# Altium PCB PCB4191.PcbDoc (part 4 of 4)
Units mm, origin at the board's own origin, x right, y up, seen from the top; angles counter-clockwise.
Board outline 160 x 160 mm, 6 copper layers (Top Layer, IM1 RIS, IM2 Signal, IM3 Signal, IM4 GND, Bottom Layer), stack 1.582 mm thick; 143 components, 121 nets, 430 pads, 4983 vias.
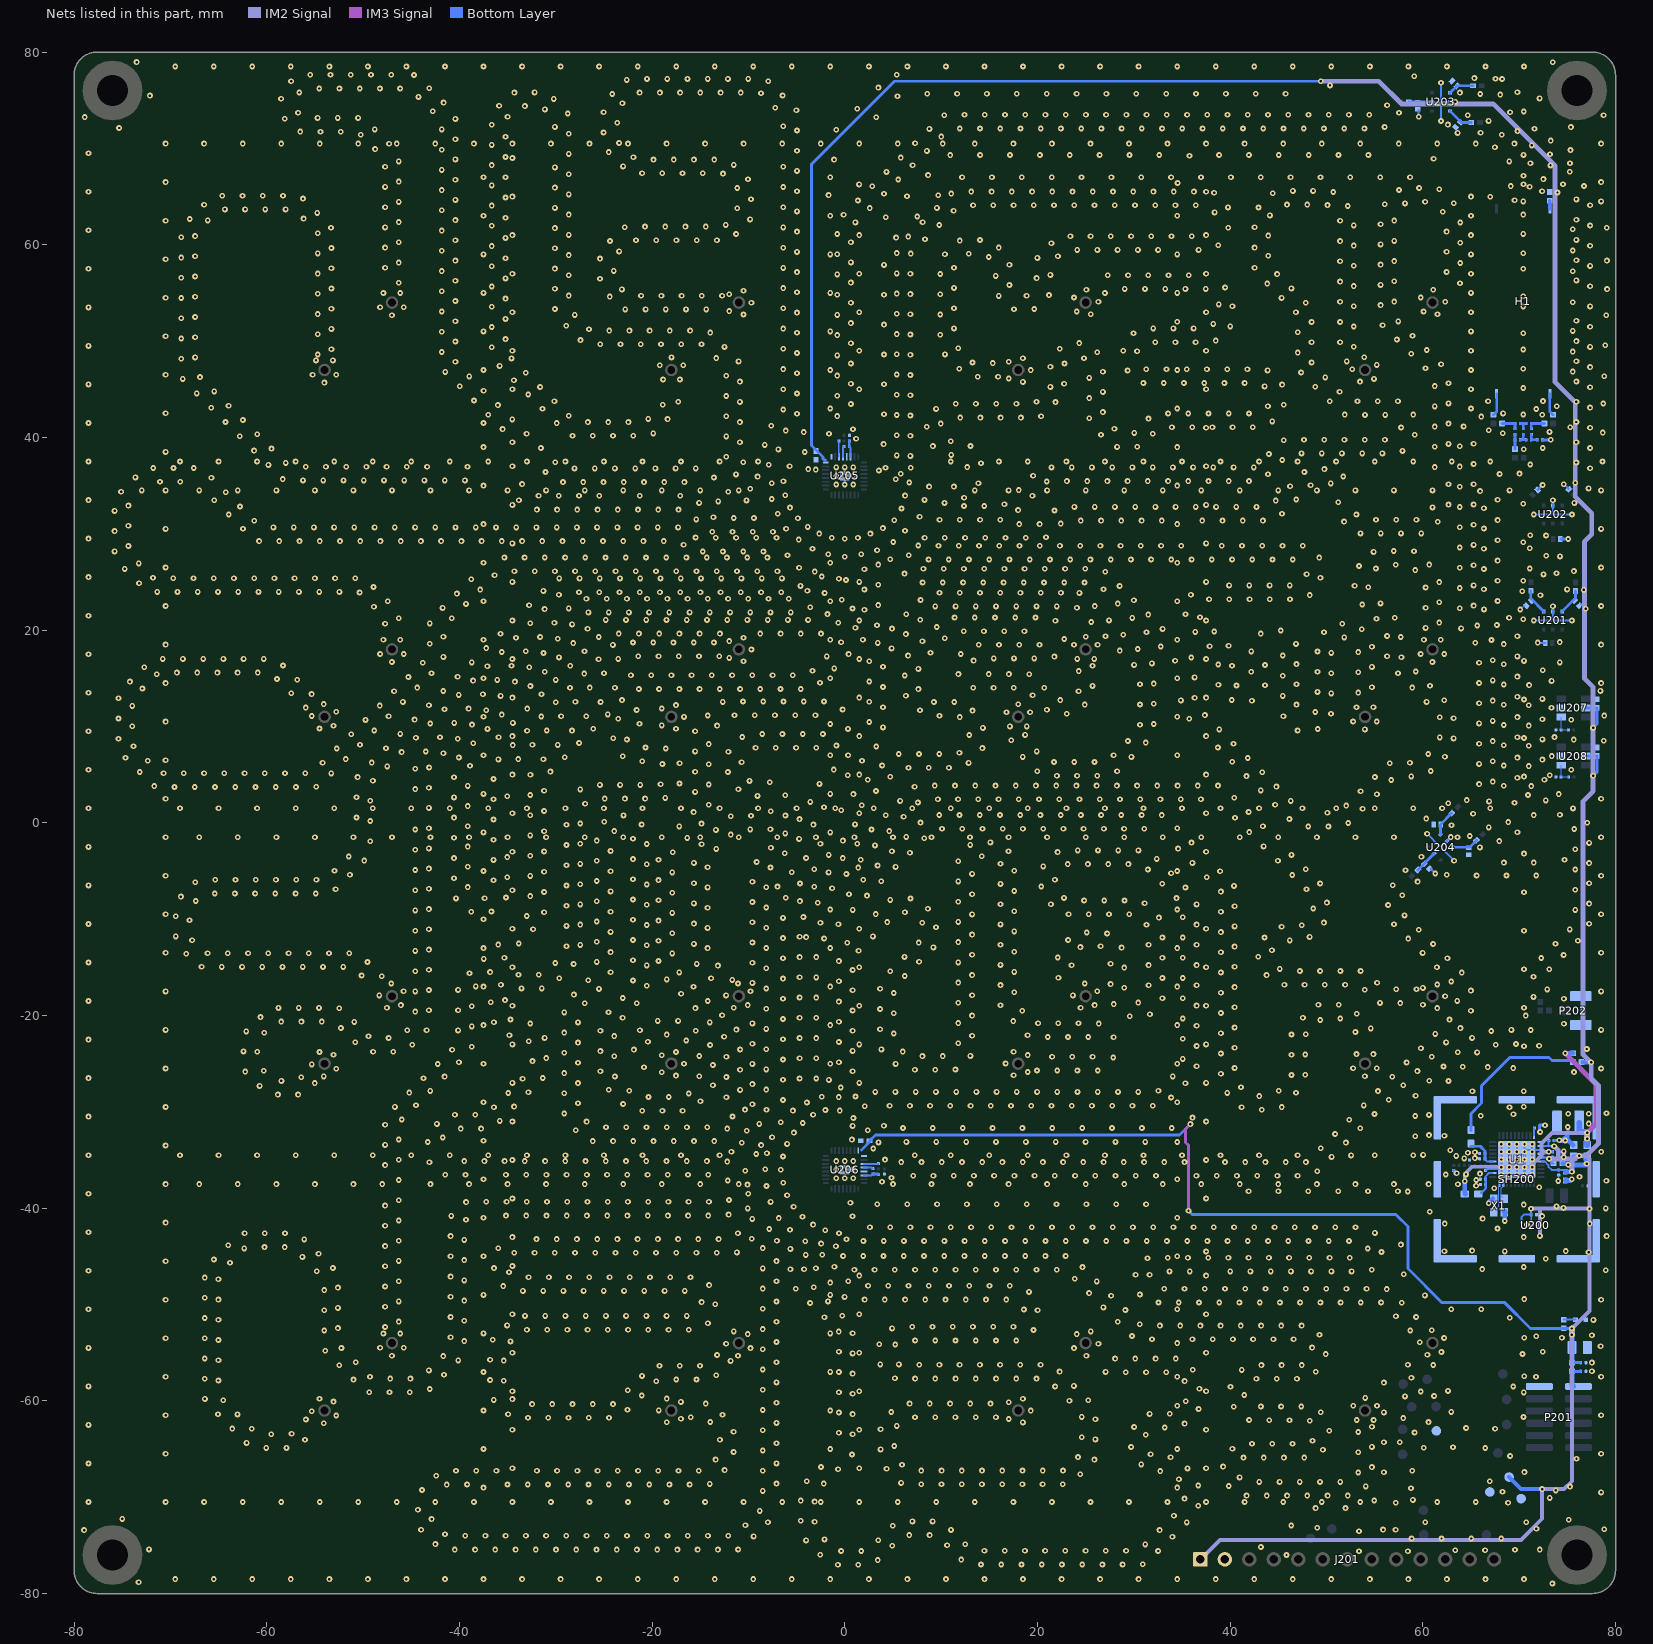
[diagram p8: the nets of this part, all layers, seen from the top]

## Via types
v1: diameter 0.6, hole 0.25, IM4 GND to Bottom Layer, tented bottom, 3953 vias
v2: diameter 0.6, hole 0.25, Top Layer to Bottom Layer, tented both sides, 851 vias
v3: diameter 0.6, hole 0.25, IM4 GND to Bottom Layer, tented both sides, 179 vias

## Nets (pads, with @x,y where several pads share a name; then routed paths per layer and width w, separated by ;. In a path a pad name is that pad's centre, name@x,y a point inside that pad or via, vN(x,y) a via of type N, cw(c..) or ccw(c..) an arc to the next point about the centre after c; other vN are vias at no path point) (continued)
GND: (continued)
  other v1: -14.877,49.663 0.637,49.77 24.333,49.787 32.213,49.888 34.313,49.888 36.413,49.888 48.45,49.876 51.413,49.879 -40.413,49.956 75.938,50.001 38.507,50.048 -27.432,50.099 57.307,50.161 -35.213,50.206 -68.862,50.268 -67.438,50.401 58.926,50.556 -0.787,50.617 9.913,50.658 6.812,50.68 -54.712,50.703 5.388,50.729 29.964,50.821 -13.969,50.876 -4.963,50.86 47.025,50.908 -41.837,50.969 65,51 -24.458,51.087 -22.358,51.087 -20.258,51.087 -18.158,51.087 -16.058,51.087 -26.553,51.235 -53.288,51.26 -6.387,51.296 32.006,51.312 34.106,51.312 36.206,51.312 11.337,51.319 -36.637,51.462 52.837,51.511 77.362,51.498 40.003,51.521 -28.916,51.584 55.822,51.646 4.069,51.708 38.252,51.784 0.637,51.87 48.45,51.976 51.413,51.979 57.441,52.041 -40.413,52.056 75.938,52.101 -35.213,52.306 -68.862,52.368 -67.438,52.501 -47.012,52.691 -28.038,52.72 -0.787,52.717 9.913,52.758 -10.516,52.763 6.812,52.78 -54.712,52.803 25.524,52.792 61.524,52.792 5.388,52.829 -4.963,52.96 46.82,52.998 65,53 -41.837,53.069 24.075,53.075 60.075,53.075 -11.991,53.113 -22.781,53.289 -20.681,53.288 -18.581,53.288 -16.481,53.288 -14.381,53.288 17.568,53.309 -30.087,53.327 19.668,53.332 -53.288,53.36 -6.387,53.396 11.337,53.419 -48.237,53.516 -45.787,53.516 -36.637,53.562 77.362,53.598 40.237,53.608 52.837,53.611 55.613,53.735 38.813,53.808 0.637,53.97 -9.691,53.988 47.845,53.987 51.413,54.079 26.32,54.082 57.037,54.102 62.32,54.082 -40.413,54.156 -35.213,54.406 -68.862,54.468 45.335,54.483 23.792,54.524 59.792,54.524 -67.438,54.601 -24.404,54.621 15.982,54.686 -21.139,54.712 -19.039,54.712 -16.939,54.712 -14.839,54.712 -12.739,54.712 18.872,54.712 -28.663,54.725 21.196,54.772 -0.787,54.817 4.069,54.808 -11.991,54.863 9.913,54.858 6.812,54.88 -54.712,54.903 5.388,54.929 -47.887,54.991 -46.137,54.991 27,54.993 65,55 -4.963,55.06 -41.837,55.169 -10.516,55.213 25.082,55.32 61.082,55.32 -23.135,55.367 -30.087,55.427 29.058,55.413 31.158,55.413 33.258,55.413 35.358,55.413 37.458,55.413 -53.288,55.46 46.36,55.472 -6.387,55.496 11.337,55.519 39.47,55.563 -36.637,55.662 77.362,55.698 52.837,55.711 17.087,55.819 55.613,55.835 43.85,55.968 63.854,56.009 -46.288,56.05 0.637,56.07 51.413,56.179 57.037,56.202 -40.413,56.256 75.938,56.301 -25.412,56.463 -35.213,56.506 19.913,56.536 -68.862,56.568 -67.438,56.701 15.663,56.761 -28.663,56.825 27.301,56.837 29.401,56.837 31.501,56.837 33.601,56.837 35.701,56.837 21.337,56.867 -0.787,56.917 9.913,56.958 44.875,56.957 6.812,56.98 65,57 -54.712,57.003 5.388,57.029 -4.963,57.16 62.463,57.166 -41.837,57.269 -23.988,57.286 -30.087,57.527 -53.288,57.56 -47.712,57.602 -6.387,57.596 42.538,57.608 11.337,57.619 -36.637,57.762 52.837,57.811 77.362,57.798 4.069,57.908 17.087,57.919 55.613,57.935 63.887,58.109 -46.288,58.15 0.637,58.17 51.413,58.279 57.037,58.302 -40.413,58.356 75.938,58.401 -25.412,58.563 -35.213,58.606 19.995,58.635 -68.862,58.668 14.936,58.732 -67.438,58.801 22.122,58.815 43.962,58.848 -28.663,58.925 10.395,59.002 65,59 -0.787,59.017 6.837,59.08 12.862,59.063 -54.712,59.103 5.388,59.129 -4.963,59.26 62.463,59.266 -23.432,59.311 -41.837,59.369 24.12,59.463 26.22,59.463 28.32,59.463 30.42,59.463 32.52,59.463 36.72,59.463 -30.087,59.627 -53.288,59.66 -47.712,59.702 -6.387,59.696 15.979,59.703 42.538,59.708 -36.637,59.862 52.837,59.911 77.362,59.898 38.761,59.954 55.613,60.035 21.446,60.153 63.887,60.209 -46.288,60.25 0.637,60.27 51.413,60.379 -24.371,60.387 57.037,60.402 -40.413,60.456 11.932,60.433 -21.676,60.463 -19.576,60.463 -17.476,60.463 -15.376,60.463 -13.276,60.463 14.031,60.487 75.938,60.501 8.322,60.565 -35.213,60.706 5.324,60.743 -68.862,60.768 6.592,60.849 23.413,60.887 25.513,60.887 27.613,60.887 29.713,60.887 31.813,60.887 33.913,60.887 36.013,60.887 -67.438,60.901 43.962,60.948 65,61 -28.663,61.025 -11.279,61.114 -0.787,61.117 -54.712,61.203 -4.963,61.36 62.463,61.366 -41.837,61.469 -30.087,61.727 -53.329,61.76 39.812,61.772 -47.712,61.802 -6.387,61.796 -22.839,61.824 42.538,61.808 -20.74,61.887 -18.64,61.887 -16.54,61.887 -14.44,61.887 -36.637,61.962 77.362,61.998 52.837,62.011 9.807,62.05 -12.347,62.06 55.613,62.135 63.887,62.309 1.1,62.318 8.077,62.334 -46.288,62.35 51.413,62.479 57.037,62.502 -66.113,62.53 -40.413,62.556 75.938,62.601 -9.825,62.628 -67.983,62.675 -56.171,62.714 -35.213,62.806 4.262,62.846 7.516,62.935 65,63 44.124,63.042 -0.123,63.109 -28.663,63.125 -54.75,63.307 38.388,63.359 62.064,63.428 -4.963,63.46 11.292,63.535 -41.837,63.569 -64.345,63.663 -62.245,63.663 -60.145,63.663 -58.045,63.663 -11.162,63.793 2.585,63.803 -30.087,63.827 9.562,63.819 39.773,63.872 42.937,63.869 -47.712,63.902 -6.387,63.896 52.215,64.017 -36.637,64.062 13.318,64.088 15.418,64.088 17.518,64.088 19.618,64.088 21.718,64.088 23.818,64.088 25.918,64.088 28.018,64.088 30.118,64.088 32.218,64.088 34.318,64.088 36.418,64.088 77.362,64.098 50.1,64.118 -66.498,64.16 45.9,64.163 48,64.163 56.035,64.192 58.144,64.287 63.211,64.297 -46.288,64.45 60.237,64.463 1.361,64.594 69.519,64.613 -40.413,64.656 75.938,64.701 -9.738,64.727 -56.235,64.792 -35.213,64.906 65,65 66.989,64.979 6.454,65.038 -64.614,65.087 -62.514,65.087 -60.414,65.087 -58.314,65.087 9.708,65.127 -1.677,65.149 -28.663,65.225 4.07,65.288 11.047,65.304 44.422,65.354 38.333,65.401 50.706,65.477 13.136,65.512 15.236,65.512 17.336,65.512 19.436,65.512 21.536,65.512 23.636,65.512 25.736,65.512 27.836,65.512 29.936,65.512 32.036,65.512 34.136,65.512 36.236,65.512 -4.963,65.56 46.509,65.587 48.609,65.587 -41.837,65.669 57.52,65.677 61.706,65.761 59.609,65.887 -11.162,65.893 -30.087,65.927 -47.712,66.002 -6.387,65.996 71.082,66.016 2.846,66.079 76.731,66.101 -36.637,66.162 74.545,66.273 -46.288,66.55 -40.413,66.756 5.555,66.773 -10.046,66.804 72.516,66.813 -35.213,67.006 12.173,67.006 15.273,67.006 18.373,67.006 21.473,67.006 24.573,67.006 27.673,67.006 30.773,67.006 33.873,67.006 36.973,67.006 40.073,67.006 43.173,67.006 46.273,67.006 49.373,67.006 52.473,67.006 55.573,67.006 58.673,67.006 70.445,67.16 8.646,67.23 -28.663,67.325 -12.641,67.384 -21.041,67.413 -18.941,67.413 -16.841,67.413 -14.741,67.413 4.331,67.564 75.246,67.586 -4.963,67.66 -41.837,67.769 -30.087,68.027 -47.712,68.102 -6.387,68.096 -23.014,68.132 73.25,68.237 -36.637,68.262 7.04,68.258 -11.531,68.289 71.162,68.458 -46.288,68.65 68.96,68.645 -19.858,68.837 -17.758,68.837 -15.658,68.837 -13.558,68.837 -1.11,68.839 -40.413,68.856 61.113,68.919 5.816,69.049 -21.945,69.077 -35.213,69.106 10.948,69.306 14.048,69.319 17.148,69.319 20.248,69.319 23.348,69.319 26.448,69.319 29.548,69.319 32.648,69.319 38.848,69.319 41.948,69.319 45.048,69.319 48.148,69.319 51.248,69.319 54.348,69.319 73.198,69.388 -28.663,69.425 -24.499,69.617 8.525,69.742 -4.963,69.76 75.325,69.825 -41.837,69.869 -48.756,69.924 67.475,70.13 71.31,70.307 -36.637,70.362 -47.305,70.487 7.301,70.533 -23.43,70.562 73.286,70.812 -40.413,70.956 -35.213,71.206 10.01,71.227 -50.241,71.409 68.192,71.428 -28.663,71.525 65.99,71.615 -25.037,71.647 -56.515,71.741 -54.415,71.738 -52.315,71.738 69.825,71.792 -4.963,71.86 -0.892,71.931 -48.79,71.972 -41.837,71.969 8.786,72.018 71.586,72.046 11.934,72.069 14.034,72.069 16.134,72.069 18.234,72.069 20.334,72.069 22.434,72.069 24.534,72.069 26.634,72.069 28.734,72.069 30.834,72.069 32.934,72.069 35.034,72.069 37.134,72.069 39.234,72.069 41.334,72.069 43.434,72.069 45.534,72.069 47.634,72.069 49.734,72.069 51.834,72.069 53.934,72.069 -30.087,72.227 56.028,72.222 -6.387,72.296 -36.637,72.462 -23.613,72.654 66.825,72.85 -58.135,73.078 -40.413,73.056 -54.72,73.162 -52.62,73.162 -50.52,73.162 3.274,73.223 -34.998,73.295 10.327,73.445 64.65,73.45 12.426,73.494 14.526,73.494 16.626,73.494 18.726,73.494 20.826,73.494 22.926,73.494 25.026,73.494 27.126,73.494 29.226,73.494 31.326,73.494 33.426,73.494 35.526,73.494 37.626,73.494 39.726,73.494 41.826,73.494 43.926,73.494 46.026,73.494 48.126,73.494 50.226,73.494 52.326,73.494 54.426,73.494 -28.751,73.623 -56.748,73.706 57.527,73.693 -25.037,73.747 69.057,73.747 70.482,73.832 -42.762,73.855 -5.024,73.959 -31.132,74.049 1.3,74.123 -7.211,74.228 -33.204,74.388 -35.885,74.423 56.287,74.468 -23.082,74.686 -41.647,74.755 -30.205,75.138 -58.512,75.143 -44.247,75.34 5.466,75.415 -6.459,75.492 68.036,75.582 -24.138,75.644 8.556,75.669 11.656,75.669 14.756,75.669 17.856,75.669 20.956,75.669 24.056,75.669 27.156,75.669 30.256,75.669 33.356,75.669 36.456,75.669 39.556,75.669 42.656,75.669 45.756,75.669 65.95,75.65 -8.696,75.713 -34.294,75.794 -21.294,75.788 -19.194,75.788 -17.094,75.788 -14.994,75.788 -12.894,75.788 -10.794,75.788 63.85,75.795 -56.616,75.802 -32.194,75.812 69.81,75.822 -54.557,76.213 -52.457,76.213 -50.357,76.213 -48.257,76.213 -46.157,76.213 -43.132,76.24 3.492,76.315 50.361,76.539 -57.467,76.965 -7.944,76.977 -22.628,77.104 -20.531,77.212 -18.431,77.212 -16.331,77.212 -14.231,77.212 -12.131,77.212 -10.031,77.212 67.537,77.219 68.224,77.198 65.35,77.3 -44.718,77.616 -55.478,77.637 -53.378,77.637 -51.278,77.637 -49.178,77.637 -47.078,77.637 5.39,77.655
  other v2: 73.448,-78.959 -73.299,-78.823 -69.5,-78.5 -65.5,-78.5 -61.5,-78.5 -57.5,-78.5 -53.5,-78.5 -49.5,-78.5 -45.5,-78.5 -41.5,-78.5 -37.5,-78.5 -33.5,-78.5 -29.5,-78.5 -25.5,-78.5 -21.5,-78.5 -17.5,-78.5 -13.5,-78.5 -9.5,-78.5 -5.5,-78.5 -1.5,-78.5 2.5,-78.5 6.5,-78.5 10.5,-78.5 14.5,-78.5 18.5,-78.5 22.5,-78.5 26.5,-78.5 30.5,-78.5 34.5,-78.5 38.5,-78.5 42.5,-78.5 46.5,-78.5 50.5,-78.5 54.5,-78.5 58.5,-78.5 62.5,-78.5 66.5,-78.5 70.5,-78.5 72.141,-75.438 -72.225,-75.417 -78.955,-73.415 78.828,-73.322 75.138,-72.336 -74.993,-72.254 68.849,-70.586 57.197,-70.575 -78.5,-70.5 -70.5,-70.5 -66.5,-70.5 -62.5,-70.5 -58.5,-70.5 -54.5,-70.5 -50.5,-70.5 -46.5,-70.5 -42.5,-70.5 -38.5,-70.5 -34.5,-70.5 -30.5,-70.5 -26.5,-70.5 -22.5,-70.5 -18.5,-70.5 -14.5,-70.5 -10.5,-70.5 -6.5,-70.5 -2.5,-70.5 1.5,-70.5 5.5,-70.5 9.5,-70.5 13.5,-70.5 17.5,-70.5 21.5,-70.5 25.5,-70.5 29.5,-70.5 33.5,-70.5 37.5,-70.5 41.5,-70.5 45.5,-70.5 49.5,-70.5 53.5,-70.5 61.5,-70.5 65.5,-70.5 73.175,-70.075 78.5,-69.5 -37.5,-69.001 34.5,-69.001 70.538,-67.39 -34.5,-67.001 37.5,-67.001 1.5,-67 -78.5,-66.5 -70.5,-65.5 78.5,-65.5 -37.5,-65.001 -1.5,-65 34.5,-65.001 -34.5,-63.001 1.5,-63 37.5,-63.001 -78.5,-62.5 70.45,-61.675 -70.5,-61.5 78.5,-61.5 -37.5,-61.001 -1.5,-61 34.5,-60.501 70.475,-59.125 -34.5,-59.001 1.5,-59 37.5,-59.001 -78.5,-58.5 34.5,-57.501 -70.5,-57.5 78.5,-57.5 70.522,-57.44 -37.5,-57.001 -1.5,-57 77.55,-56.925 77.55,-56.025 -34.5,-55.001 1.5,-55 37.5,-55.001 -78.5,-54.5 78.45,-54.325 34.5,-54.001 -70.5,-53.5 70.522,-53.44 77.55,-53.2 -37.5,-53.001 -1.5,-53 77.7,-51.6 -34.5,-51.001 1.5,-51 37.5,-51.001 -78.5,-50.5 34.5,-50.501 -70.5,-49.5 78.5,-49.5 70.522,-49.44 -37.5,-49.001 -1.5,-49 1.5,-47 37.5,-47.001 -78.5,-46.5 78.975,-46.45 70.468,-46.104 -34.5,-46.001 -70.5,-45.5 -37.5,-45.001 34.5,-45.001 37.5,-44.501 -34.5,-43.001 70.475,-43 79.075,-42.9 -0.6,-42.6 -78.5,-42.5 -70.5,-41.5 -37.5,-41.001 34.5,-41.001 0.797,-40.836 78.975,-40.025 70.475,-39.625 0.58,-39.448 -34.5,-39.001 37.5,-39.001 -78.5,-38.5 63.636,-37.519 -70.5,-37.5 -66.999,-37.5 -62.999,-37.5 -58.999,-37.5 -54.999,-37.5 -50.999,-37.5 -47.999,-37.5 -42.999,-37.5 -38.999,-37.5 -34.999,-37.5 -30.999,-37.5 -26.999,-37.5 -22.999,-37.5 -18.999,-37.5 -14.999,-37.5 -10.999,-37.5 5.001,-37.499 9.001,-37.5 13.001,-37.5 17.001,-37.5 21.001,-37.5 25.001,-37.5 29.001,-37.5 33.001,-37.5 37.001,-37.5 41.001,-37.5 45.001,-37.5 49.001,-37.5 53.001,-37.5 57.001,-37.5 60.601,-37.5 79.05,-37.15 75.45,-37.006 -37.5,-37.001 34.5,-37.001 -0.887,-36.884 0.001,-36.884 0.888,-36.884 4.85,-36.851 76.259,-36.744 62.369,-36.504 65.935,-36.412 -6.641,-36.009 -0.887,-35.997 0,-36 0.888,-35.997 -0.887,-35.109 0.001,-35.109 0.888,-35.109 -34.5,-35.001 37.5,-35.001 4.176,-34.954 63.475,-34.581 52.55,-34.525 -78.5,-34.5 -68.999,-34.5 -64.999,-34.5 -60.999,-34.5 -56.999,-34.5 -52.999,-34.5 -48.999,-34.5 -44.999,-34.5 -40.999,-34.5 -36.999,-34.5 -32.999,-34.5 -28.999,-34.5 -24.999,-34.5 -20.999,-34.5 -16.999,-34.5 -12.999,-34.5 7.25,-34.5 11.001,-34.5 15.001,-34.5 19.001,-34.5 23.001,-34.5 27.001,-34.5 31.001,-34.5 35.001,-34.5 39.001,-34.5 43.001,-34.5 47.001,-34.5 55.001,-34.5 59.001,-34.5 -9.2,-34.375 78.525,-34.15 -70.5,-33.5 34.498,-33.128 -37.5,-33.001 0.738,-32.884 0.813,-31.459 -34.5,-31.001 37.5,-31.001 -78.5,-30.5 79.059,-30.145 -0.525,-29.875 -70.5,-29.5 70.475,-29.475 -37.5,-29.001 34.5,-29.001 70.475,-27.875 -34.5,-27.001 1.499,-27 37.5,-27.001 -78.5,-26.5 -70.5,-25.5 78.5,-25.5 -37.5,-25.001 -1.501,-25 34.5,-25.001 70.5,-23.2 -34.5,-23.001 1.499,-23 37.5,-23.001 -78.5,-22.5 -70.5,-21.5 78.5,-21.5 -37.5,-21.001 -1.501,-21 34.5,-21.001 74.645,-20.848 70.5,-19.2 -34.5,-19.001 1.499,-19 37.5,-19.001 -78.5,-18.5 74.645,-18.27 -70.5,-17.5 78.5,-17.5 -37.5,-17.001 -1.501,-17 34.5,-17.001 70.5,-15.2 -34.5,-15.001 1.499,-15 37.5,-15.001 -78.5,-14.5 -70.5,-13.5 78.5,-13.5 -37.5,-13.001 -1.501,-13 34.5,-13.001 70.5,-11.2 -34.5,-11.001 1.499,-11 37.5,-11.001 -78.5,-10.5 -37.5,-10.001 -70.5,-9.5 78.5,-9.5 -1.501,-9 34.5,-9.001 70.5,-7.2 -34.5,-7.001 -78.5,-6.5 -70.5,-5.5 78.5,-5.5 -37.5,-5.001 34.5,-5.001 1.393,-4.654 70.5,-3.2 -34.5,-3.001 37.5,-3.001 -78.5,-2.5 -70.5,-1.5 -67,-1.5 -63,-1.5 -59,-1.5 -55,-1.5 -51,-1.5 -47,-1.5 -43,-1.5 -39,-1.5 -35,-1.5 -31,-1.5 -27,-1.5 -23,-1.5 -19,-1.5 -15,-1.5 -11,-1.5 -7,-1.5 -3,-1.5 1,-1.5 5,-1.5 9,-1.5 13,-1.5 17,-1.5 21,-1.5 25,-1.5 29,-1.5 33,-1.5 37,-1.5 41,-1.5 45,-1.5 49,-1.5 53,-1.5 57,-1.5 63.6,-1.5 78.5,-1.5 -37.501,-1 -1.501,-1 71.5,0.8 -34.501,1 1.499,1 37.499,1 -78.5,1.5 -69,1.5 -65,1.5 -61,1.5 -57,1.5 -53,1.5 -49,1.5 -45,1.5 -41,1.5 -37,1.5 -33,1.5 -29,1.5 -25,1.5 -21,1.5 -17,1.5 -13,1.5 -9,1.5 -5,1.5 -1,1.5 3,1.5 7,1.5 11,1.5 15,1.5 19,1.5 23,1.5 27,1.5 31,1.5 35,1.5 39,1.5 43,1.5 47.5,1.5 51,1.5 55,1.5 59,1.5 62,1.501 67,1.501 -70.5,2.5 78.5,2.5 -37.501,3 -1.501,3 70.5,4.8 -34.501,5 1.499,5 37.499,5 -78.5,5.5 -70.5,6.5 -37.501,7 -1.501,7 34.499,7 78.772,8.527 70.5,8.8 -34.501,9 1.499,9 37.499,9 -78.5,9.5 -1.501,10.25 -70.5,10.5 -37.501,11 34.499,11 78.833,11.124 70.5,12.8 -34.501,13 1.499,13 37.499,13 -78.5,13.5 78.431,13.693 -70.5,14.5 78.5,14.5 -37.501,15 -1.501,15 34.499,15 70.5,16.8 -34.501,17 1.499,17 37.499,17 -78.5,17.5 -70.5,18.5 78.5,18.5 -37.501,19 -1.501,19 34.499,19 -34.501,21 1.499,21 37.499,21 70.415,21.12 -78.5,21.5 -70.5,22.5 78.5,22.5 -37.501,23 -1.501,23 34.499,23 -34.501,25 1.499,25 37.499,25 70.415,25.12 -78.5,25.5 -70.5,26.5 78.5,26.5 -37.501,27 -1.501,27 34.499,27 0.006,27.625 -34.501,29 37.499,29 70.415,29.12 -0.001,29.475 -78.5,29.5 -70.5,30.5 78.5,30.5 -37.501,31 34.499,31 -34.501,33 37.499,33 70.415,33.12 -78.5,33.5 65.939,34.425 -70.5,34.5 -67,34.5 -63,34.5 -59,34.5 -55,34.5 -51,34.5 -47,34.5 -43,34.5 -39,34.5 -35,34.5 -31,34.5 -27,34.5 -23,34.5 -19,34.5 -15,34.5 -11,34.5 13.5,34.5 17,34.5 21,34.5 25,34.5 29,34.5 33,34.5 37,34.5 41,34.5 45,34.5 49,34.5 53,34.5 57,34.5 61,34.5 69,34.5 78.5,34.5 -37.501,35 34.499,35 -0.887,35.116 0,35.116 0.888,35.116 -6.375,35.45 -0.887,36.003 0,36 0.888,36.003 3.538,36.566 -3.012,36.666 -3.787,36.716 4.227,36.841 6.85,36.849 -0.887,36.891 0,36.891 0.888,36.891 -34.501,37 37.499,37 -78.5,37.5 -69,37.5 -65,37.5 -61,37.5 -57,37.5 -53,37.5 -49,37.5 -45,37.5 -41,37.5 -37,37.5 -33,37.5 -29,37.5 -25,37.5 -21,37.5 -17,37.5 -13,37.5 -9,37.5 11,37.5 16,37.5 19,37.5 23,37.5 27,37.5 31,37.5 35,37.5 39,37.5 43,37.5 47,37.5 51,37.5 55,37.5 59,37.5 63,37.5 67,37.5 78.65,37.5 -70.5,38.5 70.475,38.775 -37.501,39 34.499,39 -34.501,39.5 78.675,40.5 0.85,40.849 37.499,41 -78.5,41.5 -37.501,41.5 70.425,42.375 -70.5,42.5 -1.501,43 34.499,43 78.725,43.525 -34.501,45 1.499,45 37.499,45 70.423,45.127 -78.5,45.5 78.825,46.35 -70.5,46.5 75.552,46.829 -37.501,47 -1.501,47 34.499,47 70.423,47.127 75.552,48.911 -34.501,49 1.499,49 37.499,49 70.423,49.127 -78.5,49.5 78.925,49.575 -70.5,50.5 70.423,50.82 -37.501,51 -1.501,51 75.552,51.058 34.499,52 79.025,52.675 -34.501,53 1.499,53 37.499,53 -78.5,53.5 70.423,53.587 75.552,54.032 -70.5,54.5 70.423,54.65 -37.501,55 -1.501,55 34.499,55 79.125,55.4 -34.501,57 1.499,57 37.499,57 75.552,57.253 -78.5,57.5 70.423,57.503 79.1,58.35 -70.5,58.5 -37.501,59 -1.501,59 34.499,59 70.423,59.127 75.552,59.401 -34.501,61 1.499,61 37.499,61 70.423,61.127 -78.5,61.5 75.552,61.614 79.083,61.77 -70.5,62.5 -37.501,63 -1.501,63 34.499,63 70.423,63.127 70.423,64.495 78.5,64.5 -34.501,65 -78.5,65.5 37.499,65.5 1.487,66.266 70.443,66.279 34.546,66.412 -70.5,66.5 78.5,66.5 -37.501,67 -1.501,67 75.27,68.461 -34.501,69 35.781,69.227 70.45,69.325 -78.5,69.5 -70.5,70.5 -66.5,70.5 -62.5,70.5 -58.5,70.5 -54.5,70.5 -50.5,70.5 -46.5,70.5 -42.5,70.5 -38.5,70.5 -34.5,70.5 -30.5,70.5 -26.5,70.5 -22.5,70.5 -18.5,70.5 -14.5,70.5 -10.5,70.5 -6.5,70.5 -2.5,70.5 1.5,70.5 5.5,70.5 10.175,70.5 13.5,70.5 17.5,70.5 21.5,70.5 25.5,70.5 29.5,70.5 33.5,70.5 37.5,70.5 41.5,70.5 45.5,70.5 49.5,70.5 53.5,70.5 57.5,70.5 61.5,70.5 65.5,70.5 69.5,70.5 78.5,70.5 -75.321,72.118 75.365,72.209 62.605,72.475 -78.886,73.249 78.765,73.444 72.119,75.184 -72.122,75.479 59.099,77.488 -69.5,78.5 -65.5,78.5 -61.5,78.5 -57.5,78.5 -53.5,78.5 -49.5,78.5 -45.5,78.5 -41.5,78.5 -37.5,78.5 -33.5,78.5 -29.5,78.5 -25.5,78.5 -21.5,78.5 -17.5,78.5 -13.5,78.5 -9.5,78.5 -5.5,78.5 -1.5,78.5 2.5,78.5 6.5,78.5 10.5,78.5 14.5,78.5 18.5,78.5 22.5,78.5 26.5,78.5 30.5,78.5 34.5,78.5 38.5,78.5 42.5,78.5 46.5,78.5 50.5,78.5 54.5,78.5 58.5,78.5 62.5,78.5 66.5,78.5 70.5,78.5 -73.504,78.959 73.473,78.951
  other v3: 57.166,-73.37 60.259,-72.609 58.97,-70.278 68.264,-69.435 73.805,-69.296 75.278,-68.904 66.948,-68.338 58.897,-67.259 75.953,-66.02 69.057,-65.725 60.087,-64.879 66.48,-64.891 63.13,-64.817 57.608,-64.29 59.142,-63.284 67.498,-62.903 64.492,-62.817 60.59,-62.204 57.964,-61.787 62.958,-61.149 58.148,-59.541 61.167,-59.492 59.78,-59.026 69.393,-58.509 71.747,-57.494 70.348,-55.134 72.446,-54.912 66.175,-46.326 77.2,-44.566 62.241,-44.471 68.508,-44.488 74.831,-44.452 65.108,-44.4 -2.46,-43.681 -4.105,-43.442 -2.037,-42.284 -5.683,-42.248 -3.287,-41.709 62.268,-41.604 77.32,-41.602 66.2,-41.081 -6.851,-41.033 -4.387,-40.884 72.375,-40.825 74.598,-39.97 -5.312,-39.859 73.874,-39.814 -7.699,-39.348 -5.987,-38.659 67.4,-37.931 72.075,-37.831 -8.124,-37.702 65.525,-37.681 -6.387,-37.359 3.86,-37.255 65.55,-37.075 64.475,-36.5 -8.265,-35.953 64.3,-34.831 65.4,-34.806 -6.412,-34.634 -8.085,-34.294 64.675,-34.256 65.4,-34.206 62.85,-33.981 2.944,-33.808 -5.987,-33.334 -7.545,-32.648 62.237,-32.475 -5.287,-32.159 72.174,-32.097 77.225,-31.225 -4.362,-31.159 -6.651,-31.091 -3.287,-30.309 69.4,-30.25 75.1,-30.2 77.225,-30.2 -5.385,-29.87 -2.012,-29.809 68.991,-29.534 2.075,-29.433 -3.931,-29.034 -0.625,-28.475 -2.388,-28.43 77.024,-23.476 72.067,-23.14 62.972,-0.25 60.36,0.437 62.644,2.029 73.168,4.925 75.398,5.51 73.368,6.925 75.662,8.634 73.664,8.892 75.398,10.699 73.35,11.95 -1.71,27.871 1.702,27.876 3.348,28.3 -3.352,28.454 5.033,29.149 -4.775,29.4 -1.362,29.591 1.363,29.591 -2.662,30.016 2.663,30.016 6.247,30.316 -6.094,30.515 3.956,30.593 -3.837,30.716 5.136,31.397 -4.862,31.616 -6.966,32.068 5.888,32.619 -5.687,32.716 -7.571,33.612 6.263,33.966 -6.175,34 5.28,35.659 72.448,38.899 1.173,39.855 71.761,42.954 73.975,65.425 72.375,65.55 69.127,66.09
N16816371: L201.1 U1.31
N16816400: C217.1 U1.30 | length 0.8
  Bottom Layer w0.2: U1.30@71.55,-32.455 C217.1@71.55,-31.65
N16816410: U1.9 X1.3 | length 1.6
  Bottom Layer w0.1: X1.3@68.291,-38.891 68.15,-38.75 68.15,-38.477 68.15,-37.95 68.35,-37.75 U1.9@68.35,-37.445
N16816441: U1.10 X1.1 | length 2.5
  Bottom Layer w0.1: X1.1@67.7,-40.025 67.9,-39.825 67.9,-38.56 U1.10@67.9,-37.667 ; U1.10@67.925,-37.642 U1.10@67.95,-37.667
N16816744: C204.1 C205.1 L202.2 U1.12 | length 2.8
  Bottom Layer w0.2: C204.1@66.525,-37 66.51,-36.985 66.51,-36.69 66.85,-36.35 U1.12@67.255,-36.35
  Bottom Layer w0.25: L202.2@66.05,-38.425 66.525,-37.95 C205.1@66.525,-37.55 66.525,-37.038 C204.1@66.544,-37.019
N16816775: C206.1 C207.1 L203.2 U1.15 | length 3.5
  Bottom Layer w0.2: C206.1@66.45,-34.881 66.45,-34.963 66.638,-35.151 U1.15@67.255,-35.151
  Bottom Layer w0.3: L203.2@65,-33.575 65.95,-33.575 66.45,-34.075 C206.1@66.45,-34.906
N16857153: CC11.2 D11.2 U201.3 | length 2.7
  Bottom Layer w0.28: U201.3@74.45,21.929 75.838,23.317 CC11.2@75.838,24.054
N16857156: CC12.2 D12.2 U201.1 | length 2.7
  Bottom Layer w0.28: CC12.2@71.212,24.074 71.212,23.267 U201.1@72.55,21.929
N16857328: H1.2 RH1.1 | length 0.8
  Bottom Layer w0.35: H1.2@73.185,63.746 RH1.1@73.185,64.56
N16857331: CH1.1 LH1.1 R209.1 | length 1.5
  Bottom Layer w0.28: R209.1@69.567,38.789 CH1.1@69.567,39.753 ; CH1.1@69.567,39.753 LH1.1@69.567,40.303
N16857342: CH2.1 LH1.2 R211.1 | length 1.9
  Bottom Layer w0.28: R211.1@68.22,41.45 69.565,41.45 CH2.1@69.567,41.453 LH1.2@69.567,40.903
N16857347: CH2.2 CH4.1 LH2.2 | length 1.2
  Bottom Layer w0.28: CH2.2@70.117,41.453 70.417,41.453 ; LH2.2@70.417,40.903 70.417,41.453 ; CH4.1@70.717,41.453 70.417,41.453
N16857354: CH1.2 CH3.1 LH2.1 | length 1.2
  Bottom Layer w0.28: CH1.2@70.117,39.753 70.417,39.753 ; LH2.1@70.417,40.303 70.417,39.753 ; CH3.1@70.717,39.753 70.417,39.753
N16857397: CH4.2 LH3.2 R213.1 | length 1.9
  Bottom Layer w0.28: LH3.2@71.267,40.903 CH4.2@71.267,41.453 R213.1@72.62,41.453
N16857402: H1.4 R210.1 | length 2.3
  Bottom Layer w0.28: R210.1@67.32,42.35 67.655,42.685 H1.4@67.655,44.546
N16857405: H1.3 R212.1 | length 2.3
  Bottom Layer w0.28: H1.3@73.185,44.546 73.185,42.685 R212.1@73.52,42.35
N16857668: CC31.1 D31.2 U203.3 | length 2.7
  Bottom Layer w0.28: U203.3@62.809,73.875 63.991,72.692 CC31.1@65.02,72.692
N16857679: CC32.1 D32.2 U203.1 | length 2.7
  Bottom Layer w0.28: U203.1@62.809,75.775 63.531,76.497 63.541,76.507 CC32.1@65.206,76.507
N16857715: CC41.1 D41.2 U204.3 | length 2.7
  Bottom Layer w0.28: U204.3@63.169,-2.552 64.841,-2.552 CC41.1@65.568,-1.825
N16857764: CC42.1 D42.2 U204.1 | length 2.7
  Bottom Layer w0.28: U204.1@61.825,-1.209 61.825,-0.769 61.825,-0.188 61.825,-0.173 61.83,-0.168 CC42.1@63.002,1.004
N16857781: CC33.2 D33.2 U203.5 | length 2.4
  Bottom Layer w0.28: CC33.2@58.551,74.825 U203.5@60.951,74.825
N16857793: L11.2 U205.3 | length 1.6
  Bottom Layer w0.2: U205.3@-0.625,38.01 L11.2@-0.625,39.625
N16857806: R214.1 R215.2 U205.6 | length 1.7
  Bottom Layer w0.2: R214.1@0.45,39.05 0.6,38.9 U205.6@0.6,37.985
  Bottom Layer w0.28: R214.1@0.45,39.05 R215.2@0.45,39.625
N16857833: R214.2 U205.4 | length 1.1
  Bottom Layer w0.2: U205.4@-0.2,37.985 -0.2,38.937 R214.2@-0.087,39.05
N16857836: CC43.2 D43.2 U204.5 | length 2.4
  Bottom Layer w0.28: CC43.2@59.486,-4.891 U204.5@61.183,-3.195
N16857848: L21.2 U206.3 | length 1.5
  Bottom Layer w0.2: U206.3@1.985,-35.4 L21.2@3.497,-35.4
N16857851: R216.1 R217.2 U206.6 | length 1.6
  Bottom Layer w0.2: U206.6@1.985,-36.6 2.778,-36.6 R216.1@2.922,-36.456 R216.1@2.928,-36.45
  Bottom Layer w0.28: R216.1@2.928,-36.45 R217.2@3.497,-36.45
N16857888: R216.2 U206.4 | length 1
  Bottom Layer w0.2: U206.4@1.985,-35.8 2.816,-35.8 R216.2@2.922,-35.906
N17007322: CH3.2 LH3.1 RH2.1 | length 1.2
  Bottom Layer w0.28: LH3.1@71.267,40.303 CH3.2@71.267,39.753 RH2.1@71.867,39.753
N17033218: LED1.2 R202.2 | length 1.2
  Bottom Layer w0.2: R202.2@74.625,-51.575 LED1.2@75.85,-51.575
N17041538: C222.2 R207.2 U208.1 | length 2
  Bottom Layer w0.1: U208.1@74.355,5.973 74.354,5.971 C222.2@74.354,4.759 R207.2@75.143,4.759
N17041550: C221.2 R206.2 U207.1 | length 2.1
  Bottom Layer w0.1: U207.1@74.355,10.973 C221.2@74.355,9.639 R206.2@75.105,9.639
PAVDD: L203.1 R203.1 R204.2 | length 16
  Bottom Layer w0.3: L203.1@65,-31.925 L203.1@65,-31.9 65,-30.2 66.1,-29.1 66.1,-27.3 69.025,-24.375 73.092,-24.375 73.392,-24.675 75.414,-24.675 R203.1@75.571,-24.833
TP_TDI: TPJ4.1
VDCDC: C215.1 C216.1 L201.2 L202.1 R204.1 U1.34 | length 34.8
  IM3 Signal w0.5: v2(74.772,-23.925) 77.975,-27.128 77.975,-31.25 v2(77.05,-32.175)
  IM3 Signal w0.6: v2(77.05,-32.806) v2(77.05,-32.175)
  IM2 Signal w0.4: v2(64.353,-37.202) 64.353,-36.447 65.099,-35.701 71.149,-35.701 72.326,-34.524 72.326,-34.15 ; v2(73.075,-34.15) 72.326,-34.15 ; v2@77.05,-32.2 73.401,-32.2 72.326,-33.275 72.326,-34.15
  IM2 Signal w0.6: v2(77.05,-32.806) v2(77.05,-32.175)
  Bottom Layer w0.2: U1.34@72.245,-34.35 72.772,-34.35 v2@73.024,-34.098 ; v2(73.075,-34.15) C216.1@73.475,-34.15 ; v2@73.15,-34.075 C216.1@73.45,-34.075
  Bottom Layer w0.5: v2(64.353,-37.202) 64.353,-38.478 L202.1@64.425,-38.55 ; v2(74.772,-23.925) R204.1@75.575,-23.925 ; v2(77.05,-32.806) v2@77.081,-32.806
  Bottom Layer w0.6: L201.2@76.225,-31.125 76.225,-32 76.325,-32.1 76.975,-32.1 v2(77.05,-32.175) v2(77.05,-32.806) C215.1@77.05,-33.475
VMCU: C202.1 C203.1 C209.1 C210.1 C211.1 C212.1 C213.1 C214.1 C218.1 C219.2 C220.2 C223.2 C224.2 J201.1 R201.2 R202.1 R203.2 R205.2 TPJ11.1 U1.32 U1.35 U1.36 U200.A1 U200.E3 U205.1 U205.32 U206.1 U206.32 U207.5 U208.5 | length 438.6
  IM3 Signal w0.3: v2(35.675,-40.275) 35.675,-33.475 35.375,-33.175 35.375,-31.775 v2(35.875,-31.275)
  IM2 Signal w0.4: J201.1@36.91,-76.45 38.935,-74.425 70.2,-74.425 72.382,-72.243 v2(72.382,-69.164) 74.653,-69.164 75.469,-68.347 v2(75.469,-53.137) ; v2(71.225,-40.05) 72.15,-40.05 ; v2(72.15,-42.875) 72.15,-40.05 ; v2(75.475,-52.486) 77.28,-50.682 v2@77.28,-40.05 ; v2(76.229,-34.552) 76.368,-34.552 76.37,-34.55 v2@76.372,-34.552 ; 76.925,-34.55 76.927,-34.552 77.28,-34.905 v2@77.28,-40.05 ; v2(77.3,-40.05) v2@77.28,-40.05 ; 72.15,-40.05 v2@77.28,-40.05
  IM2 Signal w0.5: v2(49.4,76.975) 55.428,76.975 57.783,74.62 67.293,74.62 73.72,68.192 73.72,45.748 75.816,43.651 75.816,33.825 77.531,32.109 77.531,29.93 76.763,29.161 76.763,14.993 77.675,14.081 v2(77.675,9.85) v2(77.675,4.875) 77.675,3.267 76.611,2.203 76.611,-24.036 v2@77.463,-24.888 ; v2(73.1,-34.881) 74.046,-34.881 ; v2(73.625,-33.575) 73.65,-33.575 74.046,-33.97 74.046,-34.881 ; 75.35,-34.889 75.475,-35.014 v2(75.475,-36.225) ; v2(76.229,-34.552) 76.079,-34.552 75.75,-34.881 74.046,-34.881 ; v2@76.368,-34.552 76.372,-34.552 76.927,-34.552 76.973,-34.552 78.225,-33.3 78.225,-27.25 ; v2(77.463,-24.859) v2@77.463,-24.888 ; v2@77.463,-24.888 77.475,-24.9 77.475,-26.5 77.525,-26.55 ; 77.525,-26.55 78.225,-27.25 ; 77.525,-26.55 78.225,-27.25
  IM2 Signal w0.6: v2(75.469,-53.137) 75.469,-52.492 v2(75.475,-52.486)
  Bottom Layer w0.2: R205.2@70.225,-41.425 70.225,-40.925 70.475,-40.675 C218.1@71.225,-40.675 ; v2(71.225,-40.05) C218.1@71.225,-40.675 ; U200.A1@71.25,-41.425 C218.1@71.25,-40.675 C218.1@71.225,-40.675 ; U200.E3@72.05,-42.125 72.15,-42.225 v2@72.15,-42.85 ; U1.35@72.245,-34.75 72.82,-34.75 ; U1.32@72.245,-33.55 73.05,-33.55 ; U1.36@72.35,-35.15 72.639,-35.15 73.025,-35.536 73.025,-35.681 73.375,-36.031 C213.1@74.1,-36.031 C214.1@74.675,-36.031 ; C209.1@73.075,-32.981 73.05,-33.006 73.05,-33.55 ; C212.1@73.4,-35.15 73.4,-34.8 C211.1@73.475,-34.725 ; C211.1@73.425,-34.75 72.82,-34.75 ; C212.1@73.575,-35.375 73.445,-35.375 72.82,-34.75 ; v2(73.625,-33.575) v2@73.675,-33.575 ; v2@73.65,-33.55 73.05,-33.55
  Bottom Layer w0.3: -2.25,37.741 -2.25,37.804 ; -2.25,37.975 -2.25,37.954 ; -1.987,37.666 -2.112,37.666 -2.25,37.804 ; 1.726,-33.947 C224.2@2.748,-32.925 ; C224.2@2.563,-33.009 3.173,-32.4 34.75,-32.4 v2(35.875,-31.275) ; v2(35.675,-40.275) 36.075,-40.675 57.225,-40.675 58.45,-41.9 58.45,-46.275 61.95,-49.775 68.45,-49.775 71.161,-52.486 v2(75.475,-52.486) ; v2(49.4,76.975) 5.175,76.975 -3.448,68.352 -3.448,39.151 -2.25,37.954 ; R201.2@75.475,-56.037 C202.1@76.375,-56.037 ; U208.5@76.895,6.925 78.093,6.925 C220.2@78.097,6.928 78.097,5.297 v2(77.675,4.875) ; U207.5@76.895,11.925 78.075,11.925 C219.2@78.078,11.921 78.078,10.253 v2(77.675,9.85) ; -2.25,37.804 -2.25,37.954
  Bottom Layer w0.4: TPJ11.1@68.949,-67.907 70.206,-69.164 v2(72.382,-69.164) ; v2@75.469,-52.492 v2(75.475,-52.486)
  Bottom Layer w0.5: C214.1@74.8,-36.231 74.825,-36.206 74.845,-36.225 v2(75.475,-36.225) ; R201.2@75.475,-56.037 C203.1@75.475,-54.462 v2@75.475,-53.137 ; C210.1@75.65,-34.656 75.975,-34.656 76.081,-34.55 76.083,-34.552 v2(76.229,-34.552) ; R203.2@76.606,-24.859 v2(77.463,-24.859)
  Bottom Layer w0.6: v2(75.469,-53.137) v2@75.469,-52.492
VMCU_IN: C201.1 P201.1 R201.1 | length 2.6
  Bottom Layer w0.3: R201.1@75.475,-56.937 C201.1@76.375,-56.937
  Bottom Layer w0.5: R201.1@75.475,-56.937 75.475,-58.33 P201.1@75.657,-58.512
VRF: TPJ9.1
pads on no net: Hole1.1 Hole2.1 Hole3.1 Hole4.1 TPJ18.1 TPJ19.1 U200.C1 U205.10 U205.12 U205.29 U205.30 U205.31 U206.10 U206.12 U206.29 U206.30 U206.31

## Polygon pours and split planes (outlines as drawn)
GND on IM4 GND "L3_GND" (solid, pour order 0): -80,80 80,80 80,-80 -80,-80
GND on IM3 Signal "L2_CELL_FILL" (solid, remove dead copper, pour order 2): -80,80 80,80 80,-80 -80,-80
GND on Top Layer "Top_GND" (solid, pour order 8): -80,80 80,80 80,-80 -80,-80
GND on IM2 Signal "GND_L03_P010" (solid, remove dead copper, pour order 10): -80,80 -80,-80 80,-80 80,80
GND on IM1 RIS "GND_L02_P012" (solid, pour order 12): -80,80 -80,-80 80,-80 80,80
GND on Bottom Layer "Bottom_GND" (solid, remove dead copper, pour order 6): -80,80 80,80 80,-80 -80,-80

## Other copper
IM4 GND:
  pour cut-out: 77.493,-20.342 77.493,-18.642 75.389,-18.642 75.389,-18.91 74.093,-18.911 74.093,-20.079 75.389,-20.079 75.389,-20.341
Bottom Layer:
  region net GND: 66.125,-36.539 65.275,-36.539 65.275,-37.975 65.8,-37.975 66.125,-37.975 66.125,-37.65
  pour cut-out: 72.142,41.985 68.779,41.985 68.779,39.27 72.142,39.27
  region net VMCU: -2.4,38.05 -2.4,37.325 -1.65,37.325 -1.325,37.65 -1.325,38.125 -2.325,38.125
  pour cut-out: 66.452,-39.325 66.452,-39.628 66.75,-39.926 66.75,-41.025 66.8,-41.075 67.62,-41.075 68.29,-41.745 69,-41.745 69,-41.031 69,-38.25 67.125,-38.25 66.8,-38.575 66.8,-38.977
  region net GND: 75.515,22.272 76.556,23.314 76.764,23.314 77.377,22.701 76.602,21.926 75.818,21.926
  pour cut-out: 72.85,-32.7 72.85,-37.45 74.3,-37.45 74.3,-37.65 75.15,-37.65 75.15,-35.775 75.675,-35.25 76.6,-35.25 76.6,-32.7
  region net N16816371: 74.325,-30.006 73.45,-30.006 73.45,-31.425 71.85,-33.025 71.85,-33.3 72.65,-33.3 72.65,-32.95 73.22,-32.381 74.325,-32.381
  region net GND: 72.104,33.969 71.333,34.74 71.355,34.875 71.825,35.345 72.178,35.345 72.85,34.673
  region net GND: 74.01,29.982 74.01,28.892 75.004,28.872 75.144,29.013 75.144,29.826
  region net GND: 74.964,34.039 75.738,34.813 75.235,35.274 74.964,35.274 74.31,34.62
  region net GND: 61.365,-0.73 61.365,0.355 61.256,0.437 60.36,0.437 60.36,-0.688 60.46,-0.788
  region net GND: 60.973,-4.125 60.203,-4.896 60.225,-4.997 60.84,-5.613 61.665,-4.788 61.665,-4.713
  region net GND: 72.991,19.24 72.991,18.11 72.819,18.051 71.952,18.051 71.952,19.176 72.052,19.276
  region net GND: 70.48,23.278 71.492,22.266 71.125,21.875 70.621,21.875 69.792,22.704
  region net GND: 64.219,-3.062 65.303,-3.062 65.34,-3.172 65.34,-4.013 64.19,-4.013 64.115,-3.938
  pour cut-out: 67.33,-35.125 67.33,-35.975 62.765,-35.975 62.765,-35.125
  region net VMCU: 2.05,-33.6 1.325,-33.6 1.325,-34.35 1.65,-34.675 2.125,-34.675 2.125,-33.675
  region net GND: 63.191,72.772 63.958,72.005 63.907,71.902 63.312,71.307 62.499,72.12 62.499,72.226
  region net GND: 60.144,74.315 59.055,74.315 58.999,74.228 58.999,73.358 60.165,73.358 60.218,73.411
  region net GND: 62.822,76.439 63.59,77.206 63.571,77.341 62.937,77.975 62.142,77.18 62.142,77.038
  region net GND: 66.075,-34.131 65.875,-33.931 64.25,-33.931 64.25,-35.125 66.025,-35.125 ccw(c66.026,-35.075) 66.075,-35.075
  pour cut-out: 4.5,36 cw(c0,36) -4.5,36
  pour cut-out: 0,-40.5 cw(c0,-36) 0,-31.5
Multi-Layer:
  pour cut-out: 74.8,-74.8 80,-74.8 80,-80 74.8,-80
  pour cut-out: -74.8,-74.8 -74.8,-80 -80,-80 -80,-74.8
  pour cut-out: -74.8,74.8 -80,74.8 -80,80 -74.8,80
  pour cut-out: 74.8,74.8 74.8,80 80,80 80,74.8

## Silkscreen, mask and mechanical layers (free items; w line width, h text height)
Top Overlay:
  text "90°" at 1.344,71.525 h4.5 r90
  text "45°" at 72.95,67.5 h4.5 r90
  text "135°" at -70.275,65.575 h4.5 r90
  text "1" at -52.75,53.702 h2.5 r90
  text "2" at -16.75,53.167 h2.5 r90
  text "3" at 19.25,53.167 h2.5 r90
  text "4" at 55.25,53.107 h2.5 r90
  text "6" at -16.75,17.226 h2.5 r90
  text "5" at -52.75,17.167 h2.5 r90
  text "7" at 19.25,17.167 h2.5 r90
  text "8" at 55.25,17.167 h2.5 r90
  text "0°" at 77.5,-1.655 h4.5 r90
  text ".2G4power" at -28.725,-2.325 h1.9 r90
  text ".2G4freq" at -30.525,-2.925 h1.9 r90
  text "180°" at -74.775,-3.713 h4.5 r90
  text ".ProcessorType" at -32.35,-14.875 h1.9 r90
  text "9" at -52.75,-18.774 h2.5 r90
  text "11" at 19.25,-19.214 h2.5 r90
  text "Direction Finding Antenna Array" at -35.425,-19.55 h3.2 r90
  text "10" at -16.75,-19.75 h2.5 r90
  text "12" at 55.25,-19.75 h2.5 r90
  text "16" at 55.25,-55.69 h2.5 r90
  text "13" at -52.75,-55.75 h2.5 r90
  text "15" at 19.25,-55.75 h2.5 r90
  text "14" at -16.75,-55.809 h2.5 r90
  text "-135°" at -70.275,-73 h4.5 r90
  text "-45°" at 73,-73 h4.5 r90
  text "VMCU" at 37.215,-75 h1 r45
  text "GND" at 39.755,-75 h1 r45
  text "VCOM_TX" at 42.248,-75 h1 r45
  text "VCOM_RX" at 44.788,-75 h1 r45
  text "VCOM_RTS" at 47.328,-75 h1 r45
  text "VCOM_CTS" at 49.868,-75 h1 r45
  text "CTRL1" at 52.455,-75 h1 r45
  text "CTRL2" at 54.998,-75 h1 r45
  text "CTRL3" at 57.538,-75 h1 r45
  text "CTRL4" at 60.078,-75 h1 r45
  text "CTRL5" at 62.618,-75 h1 r45
  text "CTRL6" at 65.158,-75 h1 r45
  text "CTRL7" at 67.698,-75 h1 r45
  text "-90°" at 1.344,-77 h4.5 r90
Bottom Overlay:
  lines w0.15: -75.448,-8.577 -75.448,-9.577 -74.448,-9.577 ; -75.448,8.423 -75.448,9.423 -74.448,9.423 ; -70.45,-9.475 -69.45,-9.475 -69.45,-8.475 ; -70.45,9.525 -69.45,9.525 -69.45,8.525
  lines w0.152: 66.825,42.55 66.825,42.85 67.125,42.85 ; 66.85,41.65 66.85,41.95 ; 66.875,41.05 66.875,40.95 67.125,40.95 ; 67.525,40.95 67.775,40.95 67.775,41.05 ; 67.525,42.85 67.825,42.85 67.825,42.55 ; 67.825,42.25 67.825,41.95 68.125,41.95 ; 68.425,40.95 68.725,40.95 68.725,41.25 ; 68.425,41.95 68.725,41.95 68.725,41.65 ; 69.075,39 69.075,39.3 69.375,39.3 ; 69.1,38.1 69.1,38.4 ; 69.125,37.5 69.125,37.4 69.375,37.4 ; 69.775,37.4 70.025,37.4 70.025,37.5 ; 69.775,39.3 70.075,39.3 70.075,39 ; 70.075,38.7 70.075,38.4 70.375,38.4 ; 70.675,37.4 70.975,37.4 70.975,37.7 ; 70.675,38.4 70.975,38.4 70.975,38.1 ; 72.125,41.25 72.125,40.95 72.425,40.95 ; 72.125,41.65 72.125,41.95 72.425,41.95 ; 72.725,41.95 73.025,41.95 73.025,42.25 ; 73.025,40.975 73.325,40.975 ; 73.025,42.55 73.025,42.85 73.325,42.85 ; 73.725,42.85 74.025,42.85 74.025,42.55 ; 73.925,41 74.025,41 74.025,41.25 ; 73.925,41.9 74.025,41.9 74.025,41.65 ; 75.082,-23.714 75.082,-23.414 75.382,-23.414 ; 75.107,-24.614 75.107,-24.314 ; 75.132,-25.214 75.132,-25.314 75.382,-25.314 ; 75.782,-25.314 76.032,-25.314 76.032,-25.214 ; 75.782,-23.414 76.082,-23.414 76.082,-23.714 ; 76.082,-24.014 76.082,-24.314 76.382,-24.314 ; 76.682,-25.314 76.982,-25.314 76.982,-25.014 ; 76.682,-24.314 76.982,-24.314 76.982,-24.614
  text "HYBRID_I" at 65.7,48.525 h1.6 r90
  text "HYBRID_Q" at 77.45,48.4 h1.6 r90
  text "QWAVE" at 74.975,45.675 h1.2 r90
  text "QWAVE" at 66.625,45.575 h1.2 r90
  text "LUMPED" at 77.075,39.95 h1.2
  text "LUMPED" at 68.7,39.875 h1.2
  text "LUMPED" at 68.779,39.27 h1.2 r90
  text "HYBRID_IN" at 68.325,38.475 h1.6 r90
  text "QWAVE" at 73.175,36.25 h1.2
  text "BOARD INFO" at -75.798,9.473 h1.6 r90
  text "'.BoardName' Rev. '.BoardRevision'" at -77.275,9.45 h1.52 r90
  text "PAVDD" at 73.9,-21.075 h1.6 r90
  text "VDCDC" at 74.8,-22.475 h1.2 r90
  text "VMCU" at 78.275,-26.425 h1.2
Top Solder:
  the board outline again, w1.2
Bottom Solder:
  the board outline again, w1.2
Mechanical 1:
  the board outline again, w0.1
Drawing Top:
  drawing of 216 lines, arcs and shapes, not listed
Drawing RIS:
  drawing of 984 lines, arcs and shapes, not listed
Mechanical 5:
  lines w0.013: -72,-72 -72,-36 ; -72,-72 -36,-72 ; -72,-72 -72,72 ; -72,-72 72,-72 ; -72,-36 -72,0 ; -72,-36 -36,-36 ; -72,-36 -36,-36 ; -72,0 -36,0 ; -72,0 -72,36 ; -72,0 -36,0 ; -72,36 -72,72 ; -72,36 -36,36 ; -72,36 -36,36 ; -72,72 -36,72 ; -72,72 72,72 ; -36,-72 -36,-36 ; -36,-72 0,-72 ; -36,-72 -36,-36 ; -36,-36 -36,0 ; -36,-36 0,-36 ; -36,-36 0,-36 ; -36,-36 -36,0 ; -36,0 0,0 ; -36,0 -36,36 ; -36,0 0,0 ; -36,0 -36,36 ; -36,36 -36,72 ; -36,36 0,36 ; -36,36 0,36 ; -36,36 -36,72 ; -36,72 0,72 ; 0,-72 0,-36 ; 0,-72 0,-36 ; 0,-72 36,-72 ; 0,-36 0,0 ; 0,-36 0,0 ; 0,-36 36,-36 ; 0,-36 36,-36 ; 0,0 0,36 ; 0,0 36,0 ; 0,0 0,36 ; 0,0 36,0 ; 0,36 0,72 ; 0,36 36,36 ; 0,36 0,72 ; 0,36 36,36 ; 0,72 36,72 ; 36,-72 36,-36 ; 36,-72 72,-72 ; 36,-72 36,-36 ; 36,-36 36,0 ; 36,-36 72,-36 ; 36,-36 72,-36 ; 36,-36 36,0 ; 36,0 72,0 ; 36,0 36,36 ; 36,0 72,0 ; 36,0 36,36 ; 36,36 72,36 ; 36,36 36,72 ; 36,36 36,72 ; 36,36 72,36 ; 36,72 72,72 ; 72,-72 72,-36 ; 72,-72 72,72 ; 72,-36 72,0 ; 72,0 72,36 ; 72,36 72,72 ; -80,-80 -80,80 80,80 80,-80 -80,-80 ; -69.9,-69.9 -69.9,-38.1 -38.1,-38.1 -38.1,-69.9 -69.9,-69.9 ; -69.9,-33.9 -69.9,-2.1 -38.1,-2.1 -38.1,-33.9 -69.9,-33.9 ; -69.9,2.1 -69.9,33.9 -38.1,33.9 -38.1,2.1 -69.9,2.1 ; -69.9,38.1 -69.9,69.9 -38.1,69.9 -38.1,38.1 -69.9,38.1 ; -33.9,-69.9 -33.9,-38.1 -2.1,-38.1 -2.1,-69.9 -33.9,-69.9 ; -33.9,-33.9 -33.9,-2.1 -2.1,-2.1 -2.1,-33.9 -33.9,-33.9 ; -33.9,2.1 -33.9,33.9 -2.1,33.9 -2.1,2.1 -33.9,2.1 ; -33.9,38.1 -33.9,69.9 -2.1,69.9 -2.1,38.1 -33.9,38.1 ; 2.1,-69.9 2.1,-38.1 33.9,-38.1 33.9,-69.9 2.1,-69.9 ; 2.1,-33.9 2.1,-2.1 33.9,-2.1 33.9,-33.9 2.1,-33.9 ; 2.1,2.1 2.1,33.9 33.9,33.9 33.9,2.1 2.1,2.1 ; 2.1,38.1 2.1,69.9 33.9,69.9 33.9,38.1 2.1,38.1 ; 38.1,-69.9 38.1,-38.1 69.9,-38.1 69.9,-69.9 38.1,-69.9 ; 38.1,-33.9 38.1,-2.1 69.9,-2.1 69.9,-33.9 38.1,-33.9 ; 38.1,2.1 38.1,33.9 69.9,33.9 69.9,2.1 38.1,2.1 ; 38.1,38.1 38.1,69.9 69.9,69.9 69.9,38.1 38.1,38.1
Mechanical 6:
  drawing of 504 lines, arcs and shapes, not listed
Mechanical 7:
  drawing of 2118 lines, arcs and shapes, not listed
  text "TP12" at -80.195,72.421 h0.5
  text "TP12" at -30.395,72.421 h0.5
  text "TP12" at 19.405,72.421 h0.5
  text "TP12" at 69.205,72.421 h0.5
  text "TP2" at -88.046,71.85 h0.5
  text "TP2" at -38.246,71.85 h0.5
  text "TP2" at 11.554,71.85 h0.5
  text "TP2" at 61.354,71.85 h0.5
  text "TP8" at -90.546,71.37 h0.5
  text "TP8" at -40.746,71.37 h0.5
  text "TP8" at 9.054,71.37 h0.5
  text "TP8" at 58.854,71.37 h0.5
  text "TP15" at -79.796,69.77 h0.5
  text "TP15" at -29.996,69.77 h0.5
  text "TP15" at 19.804,69.77 h0.5
  text "TP15" at 69.604,69.77 h0.5
  text "TP6" at -87.127,69.041 h0.5
  text "TP6" at -37.327,69.041 h0.5
  text "TP6" at 12.473,69.041 h0.5
  text "TP6" at 62.273,69.041 h0.5
  text "TP7" at -89.657,69 h0.5
  text "TP7" at -39.857,69 h0.5
  text "TP7" at 9.943,69 h0.5
  text "TP7" at 59.743,69 h0.5
  text "TP14" at -79.796,67.171 h0.5
  text "TP14" at -29.996,67.171 h0.5
  text "TP14" at 19.804,67.171 h0.5
  text "TP14" at 69.604,67.171 h0.5
  text "TP5" at -90.596,66.671 h0.5
  text "TP5" at -40.796,66.671 h0.5
  text "TP5" at 9.004,66.671 h0.5
  text "TP5" at 58.804,66.671 h0.5
  text "TP4" at -87.127,66.521 h0.5
  text "TP4" at -37.327,66.521 h0.5
  text "TP4" at 12.473,66.521 h0.5
  text "TP4" at 62.273,66.521 h0.5
  text "TP10" at -80.696,64.22 h0.5
  text "TP10" at -30.896,64.22 h0.5
  text "TP10" at 18.904,64.22 h0.5
  text "TP10" at 68.704,64.22 h0.5
  text "TP17" at -90.596,64.07 h0.5
  text "TP17" at -40.796,64.07 h0.5
  text "TP17" at 9.004,64.07 h0.5
  text "TP17" at 58.804,64.07 h0.5
  text "TP11" at -79.774,61.667 h0.5
  text "TP11" at -29.974,61.667 h0.5
  text "TP11" at 19.826,61.667 h0.5
  text "TP11" at 69.626,61.667 h0.5
  text "TP13" at -81.546,60.171 h0.5
  text "TP13" at -31.746,60.171 h0.5
  text "TP13" at 18.054,60.171 h0.5
  text "TP13" at 67.854,60.171 h0.5
  text "TP9" at -78.295,59.47 h0.5
  text "TP9" at -28.495,59.47 h0.5
  text "TP9" at 21.305,59.47 h0.5
  text "TP9" at 71.105,59.47 h0.5
  text "TP3" at -88.445,58.271 h0.5
  text "TP3" at -38.645,58.271 h0.5
  text "TP3" at 11.155,58.271 h0.5
  text "TP3" at 60.955,58.271 h0.5
  text "TP18" at -97.995,56.391 h0.5
  text "TP18" at -48.195,56.391 h0.5
  text "TP18" at 1.605,56.391 h0.5
  text "TP18" at 51.405,56.391 h0.5
  text "TP1" at -88.397,55.721 h0.5
  text "TP16" at -81.897,55.721 h0.5
  text "TP1" at -38.597,55.721 h0.5
  text "TP16" at -32.097,55.721 h0.5
  text "TP1" at 11.203,55.721 h0.5
  text "TP16" at 17.703,55.721 h0.5
  text "TP1" at 61.003,55.721 h0.5
  text "TP16" at 67.503,55.721 h0.5
  text "TP19" at -100.147,55.37 h0.5
  text "TP19" at -50.347,55.37 h0.5
  text "TP19" at -0.547,55.37 h0.5
  text "TP19" at 49.253,55.37 h0.5
  text "TP20" at -102.806,48.421 h0.5
  text "TP20" at -53.006,48.421 h0.5
  text "TP20" at -3.206,48.421 h0.5
  text "TP20" at 46.594,48.421 h0.5
  text "TP12" at -80.195,7.621 h0.5
  text "TP12" at -30.395,7.621 h0.5
  text "TP12" at 19.405,7.621 h0.5
  text "TP12" at 69.205,7.621 h0.5
  text "TP2" at -88.046,7.05 h0.5
  text "TP2" at -38.246,7.05 h0.5
  text "TP2" at 11.554,7.05 h0.5
  text "TP2" at 61.354,7.05 h0.5
  text "TP8" at -90.546,6.57 h0.5
  text "TP8" at -40.746,6.57 h0.5
  text "TP8" at 9.054,6.57 h0.5
  text "TP8" at 58.854,6.57 h0.5
  text "TP15" at -79.796,4.97 h0.5
  text "TP15" at -29.996,4.97 h0.5
  text "TP15" at 19.804,4.97 h0.5
  text "TP15" at 69.604,4.97 h0.5
  text "TP6" at -87.127,4.241 h0.5
  text "TP6" at -37.327,4.241 h0.5
  text "TP6" at 12.473,4.241 h0.5
  text "TP6" at 62.273,4.241 h0.5
  text "TP7" at -89.657,4.2 h0.5
  text "TP7" at -39.857,4.2 h0.5
  text "TP7" at 9.943,4.2 h0.5
  text "TP7" at 59.743,4.2 h0.5
  text "TP14" at -79.796,2.371 h0.5
  text "TP14" at -29.996,2.371 h0.5
  text "TP14" at 19.804,2.371 h0.5
  text "TP14" at 69.604,2.371 h0.5
  text "TP5" at -90.596,1.871 h0.5
  text "TP5" at -40.796,1.871 h0.5
  text "TP5" at 9.004,1.871 h0.5
  text "TP5" at 58.804,1.871 h0.5
  text "TP4" at -87.127,1.721 h0.5
  text "TP4" at -37.327,1.721 h0.5
  text "TP4" at 12.473,1.721 h0.5
  text "TP4" at 62.273,1.721 h0.5
  text "TP10" at -80.696,-0.58 h0.5
  text "TP10" at -30.896,-0.58 h0.5
  text "TP10" at 18.904,-0.58 h0.5
  text "TP10" at 68.704,-0.58 h0.5
  text "TP17" at -90.596,-0.73 h0.5
  text "TP17" at -40.796,-0.73 h0.5
  text "TP17" at 9.004,-0.73 h0.5
  text "TP17" at 58.804,-0.73 h0.5
  text "TP11" at -79.774,-3.133 h0.5
  text "TP11" at -29.974,-3.133 h0.5
  text "TP11" at 19.826,-3.133 h0.5
  text "TP11" at 69.626,-3.133 h0.5
  text "TP13" at -81.546,-4.629 h0.5
  text "TP13" at -31.746,-4.629 h0.5
  text "TP13" at 18.054,-4.629 h0.5
  text "TP13" at 67.854,-4.629 h0.5
  text "TP9" at -78.295,-5.33 h0.5
  text "TP9" at -28.495,-5.33 h0.5
  text "TP9" at 21.305,-5.33 h0.5
  text "TP9" at 71.105,-5.33 h0.5
  text "TP3" at -88.445,-6.529 h0.5
  text "TP3" at -38.645,-6.529 h0.5
  text "TP3" at 11.155,-6.529 h0.5
  text "TP3" at 60.955,-6.529 h0.5
  text "TP18" at -97.995,-8.409 h0.5
  text "TP18" at -48.195,-8.409 h0.5
  text "TP18" at 1.605,-8.409 h0.5
  text "TP18" at 51.405,-8.409 h0.5
  text "TP1" at -88.397,-9.079 h0.5
  text "TP16" at -81.897,-9.079 h0.5
  text "TP1" at -38.597,-9.079 h0.5
  text "TP16" at -32.097,-9.079 h0.5
  text "TP1" at 11.203,-9.079 h0.5
  text "TP16" at 17.703,-9.079 h0.5
  text "TP1" at 61.003,-9.079 h0.5
  text "TP16" at 67.503,-9.079 h0.5
  text "TP19" at -100.147,-9.43 h0.5
  text "TP19" at -50.347,-9.43 h0.5
  text "TP19" at -0.547,-9.43 h0.5
  text "TP19" at 49.253,-9.43 h0.5
  text "TP20" at -102.806,-16.379 h0.5
  text "TP20" at -53.006,-16.379 h0.5
  text "TP20" at -3.206,-16.379 h0.5
  text "TP20" at 46.594,-16.379 h0.5
  text "TP12" at -80.195,-57.179 h0.5
  text "TP12" at -30.395,-57.179 h0.5
  text "TP12" at 19.405,-57.179 h0.5
  text "TP12" at 69.205,-57.179 h0.5
  text "TP2" at -88.046,-57.75 h0.5
  text "TP2" at -38.246,-57.75 h0.5
  text "TP2" at 11.554,-57.75 h0.5
  text "TP2" at 61.354,-57.75 h0.5
  text "TP8" at -90.546,-58.23 h0.5
  text "TP8" at -40.746,-58.23 h0.5
  text "TP8" at 9.054,-58.23 h0.5
  text "TP8" at 58.854,-58.23 h0.5
  text "TP15" at -79.796,-59.83 h0.5
  text "TP15" at -29.996,-59.83 h0.5
  text "TP15" at 19.804,-59.83 h0.5
  text "TP15" at 69.604,-59.83 h0.5
  text "TP6" at -87.127,-60.559 h0.5
  text "TP6" at -37.327,-60.559 h0.5
  text "TP6" at 12.473,-60.559 h0.5
  text "TP6" at 62.273,-60.559 h0.5
  text "TP7" at -89.657,-60.6 h0.5
  text "TP7" at -39.857,-60.6 h0.5
  text "TP7" at 9.943,-60.6 h0.5
  text "TP7" at 59.743,-60.6 h0.5
  text "TP14" at -79.796,-62.429 h0.5
  text "TP14" at -29.996,-62.429 h0.5
  text "TP14" at 19.804,-62.429 h0.5
  text "TP14" at 69.604,-62.429 h0.5
  text "TP5" at -90.596,-62.929 h0.5
  text "TP5" at -40.796,-62.929 h0.5
  text "TP5" at 9.004,-62.929 h0.5
  text "TP5" at 58.804,-62.929 h0.5
  text "TP4" at -87.127,-63.079 h0.5
  text "TP4" at -37.327,-63.079 h0.5
  text "TP4" at 12.473,-63.079 h0.5
  text "TP4" at 62.273,-63.079 h0.5
  text "TP10" at -80.696,-65.38 h0.5
  text "TP10" at -30.896,-65.38 h0.5
  text "TP10" at 18.904,-65.38 h0.5
  text "TP10" at 68.704,-65.38 h0.5
  text "TP17" at -90.596,-65.53 h0.5
  text "TP17" at -40.796,-65.53 h0.5
  text "TP17" at 9.004,-65.53 h0.5
  text "TP17" at 58.804,-65.53 h0.5
  text "TP11" at -79.774,-67.933 h0.5
  text "TP11" at -29.974,-67.933 h0.5
  text "TP11" at 19.826,-67.933 h0.5
  text "TP11" at 69.626,-67.933 h0.5
  text "TP13" at -81.546,-69.429 h0.5
  text "TP13" at -31.746,-69.429 h0.5
  text "TP13" at 18.054,-69.429 h0.5
  text "TP13" at 67.854,-69.429 h0.5
  text "TP9" at -78.295,-70.13 h0.5
  text "TP9" at -28.495,-70.13 h0.5
  text "TP9" at 21.305,-70.13 h0.5
  text "TP9" at 71.105,-70.13 h0.5
  text "TP3" at -88.445,-71.329 h0.5
  text "TP3" at -38.645,-71.329 h0.5
  text "TP3" at 11.155,-71.329 h0.5
  text "TP3" at 60.955,-71.329 h0.5
  text "TP18" at -97.995,-73.209 h0.5
  text "TP18" at -48.195,-73.209 h0.5
  text "TP18" at 1.605,-73.209 h0.5
  text "TP18" at 51.405,-73.209 h0.5
  text "TP1" at -88.397,-73.879 h0.5
  text "TP16" at -81.897,-73.879 h0.5
  text "TP1" at -38.597,-73.879 h0.5
  text "TP16" at -32.097,-73.879 h0.5
  text "TP1" at 11.203,-73.879 h0.5
  text "TP16" at 17.703,-73.879 h0.5
  text "TP1" at 61.003,-73.879 h0.5
  text "TP16" at 67.503,-73.879 h0.5
  text "TP19" at -100.147,-74.23 h0.5
  text "TP19" at -50.347,-74.23 h0.5
  text "TP19" at -0.547,-74.23 h0.5
  text "TP19" at 49.253,-74.23 h0.5
  text "TP20" at -102.806,-81.179 h0.5
  text "TP20" at -53.006,-81.179 h0.5
  text "TP20" at -3.206,-81.179 h0.5
  text "TP20" at 46.594,-81.179 h0.5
